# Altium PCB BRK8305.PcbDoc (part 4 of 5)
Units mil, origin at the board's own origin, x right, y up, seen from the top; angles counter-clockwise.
Board outline 5944.89 x 4139.76 mil, 4 copper layers (L1-Top, L2-GND, L3-GND, L4-BOT), stack 61.2 mil thick; 237 components, 286 nets, 1257 pads, 698 vias.
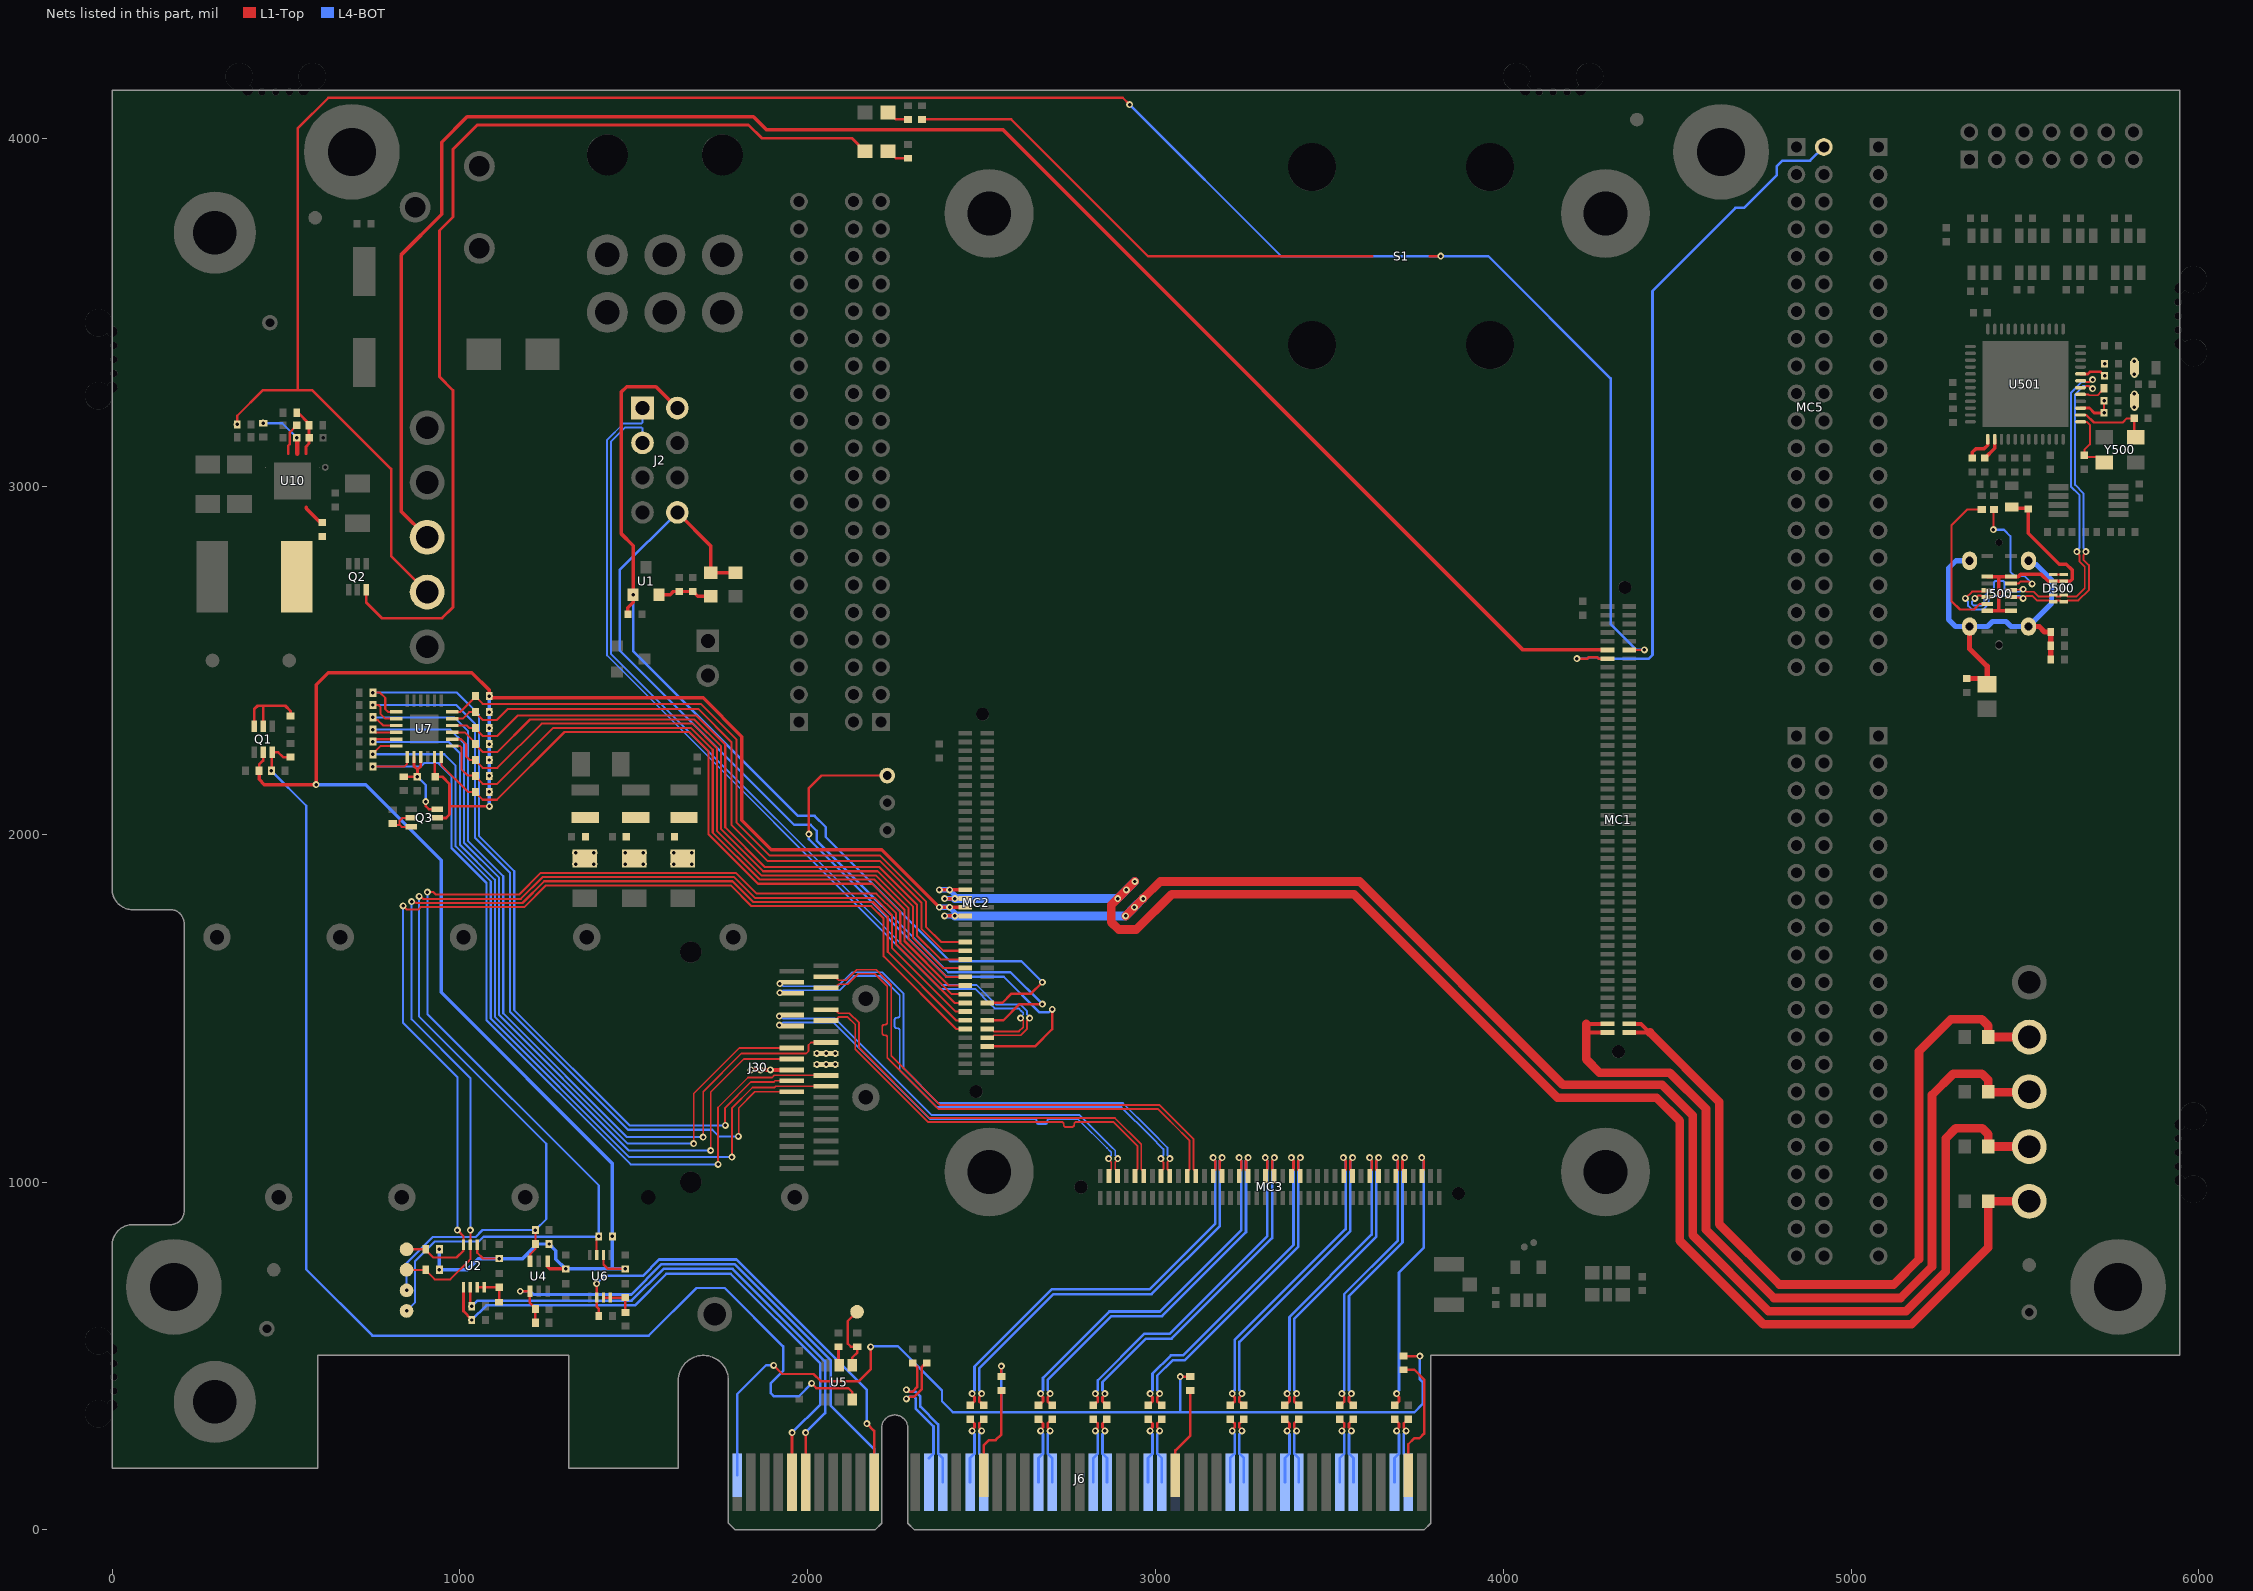
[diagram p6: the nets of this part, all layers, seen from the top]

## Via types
v1: diameter 20, hole 10, L1-Top to L4-BOT, tented both sides, 698 vias

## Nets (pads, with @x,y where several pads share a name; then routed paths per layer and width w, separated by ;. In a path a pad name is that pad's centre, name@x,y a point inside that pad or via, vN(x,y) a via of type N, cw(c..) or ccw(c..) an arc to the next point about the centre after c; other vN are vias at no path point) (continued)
MGT_TXN0_225: C20.2 MC3.47 | length 973.6
  L1-Top w7.5: v1(3011.8,391.89) 3011.8,388.51 3004.77,381.48 3004.77,369.54 3009.17,365.15 3011.22,365.15 C20.2@3017.71,358.66 ; MC3.47@3415.75,1017.72 3415.75,1030.51 3410,1036.26 3410,1061.23 3416.25,1067.48 v1(3416.25,1070.87)
  L4-BOT w7.5: v1(3011.8,391.89) 3011.8,395.27 3004.77,402.3 3004.77,443.76 3049.48,488.47 3084.32,488.47 3410,814.14 3410,1061.23 3416.25,1067.48 v1(3416.25,1070.87)
MGT_TXN0_226: J30.37 MC3.23 | length 1505.4
  L1-Top w5.25: J30.37@2052.5,1590.59 2081.05,1590.59 2085.31,1586.33 2085.31,1583.54 2088.39,1580.47 2110.73,1580.47 2140.96,1610.7 2196.61,1610.7 2239.87,1567.44 2239.87,1363.05 2381.42,1221.5 3011.81,1221.5 3108.87,1124.43 3108.87,1037.39 3115.75,1030.51 MC3.23@3115.75,1017.72
MGT_TXN1_224: C26.2 MC3.71 | length 849.1
  L1-Top w7.5: v1(3562.98,391.89) 3562.98,388.51 3555.95,381.48 3555.95,369.54 3560.35,365.15 3562.4,365.15 C26.2@3568.89,358.66 ; MC3.71@3715.75,1017.72 3715.75,1030.51 3710,1036.26 3710,1061.23 3716.25,1067.48 v1(3716.25,1070.87)
  L4-BOT w7.5: v1(3562.98,391.89) 3562.98,395.27 3555.95,402.3 3555.95,672.7 3710,826.74 3710,1061.23 3716.25,1067.48 v1(3716.25,1070.87)
MGT_TXN1_225: C18.2 MC3.41 | length 1030.4
  L1-Top w7.5: v1(2854.32,391.89) 2854.32,388.51 2847.29,381.48 2847.29,369.54 2851.69,365.15 2853.74,365.15 C18.2@2860.23,358.66 ; MC3.41@3340.75,1017.72 3340.75,1030.51 3335,1036.26 3335,1061.23 3341.25,1067.48 v1(3341.25,1070.87)
  L4-BOT w7.5: v1(2854.32,391.89) 2854.32,395.27 2847.29,402.3 2847.29,424.95 2972.63,550.29 3046.15,550.29 3335,839.14 3335,1061.23 3341.25,1067.48 v1(3341.25,1070.87)
MGT_TXN1_226: J30.2 MC3.17 | length 1559.6
  L1-Top w5.25: MC3.17@3040.75,1017.72 3040.75,1030.51 3033.87,1037.39 3033.87,1057.03 3041.25,1064.41 v1(3041.25,1067.48)
  L4-BOT w5.25: v1(1919.62,1570.72) 1922.7,1570.72 1930.07,1563.35 2086.63,1563.35 2127.05,1603.77 2213.5,1603.77 2226.52,1590.75 2275.5,1541.77 2275.5,1327.09 2375.33,1227.27 2906.39,1227.27 2984.24,1149.41 3033.87,1099.78 3033.87,1077.93 3041.25,1070.56 v1(3041.25,1067.48)
MGT_TXN2_224: C24.2 MC3.65 | length 883.3
  L1-Top w7.5: v1(3405.5,391.89) 3405.5,388.51 3398.47,381.48 3398.47,369.54 3402.87,365.15 3404.92,365.15 C24.2@3411.41,358.66 ; MC3.65@3640.75,1017.72 3640.75,1030.51 3635,1036.26 3635,1061.23 3641.25,1067.48 v1(3641.25,1070.87)
  L4-BOT w7.5: v1(3405.5,391.89) 3405.5,395.27 3398.47,402.3 3398.47,606.91 3635,843.44 3635,1061.23 3641.25,1067.48 v1(3641.25,1070.87)
MGT_TXN2_225: C16.2 MC3.35 | length 1106.7
  L1-Top w7.5: v1(2696.84,391.89) 2696.84,388.51 2689.81,381.48 2689.81,369.54 2694.21,365.15 2696.26,365.15 C16.2@2702.75,358.66 ; MC3.35@3265.75,1017.72 3265.75,1030.51 3260,1036.26 3260,1061.23 3266.25,1067.48 v1(3266.25,1070.87)
  L4-BOT w7.5: v1(2696.84,391.89) 2696.84,395.27 2689.81,402.3 2689.81,431.71 2872.92,614.81 3018.37,614.81 3260,856.44 3260,1061.23 3266.25,1067.48 v1(3266.25,1070.87)
MGT_TXN2_226: J30.34 MC3.11 | length 1204.1
  L1-Top w5.25: J30.34@2052.5,1496.1 2081.05,1496.1 2085.31,1491.84 2085.31,1489.06 2088.39,1485.98 2119.58,1485.98 2147.58,1457.98 2147.58,1386.86 2349.83,1184.61 2883.15,1184.61 2958.87,1108.88 2958.87,1037.39 2965.75,1030.51 MC3.11@2965.75,1017.72
MGT_TXN3_224: C22.2 MC3.59 | length 917.4
  L1-Top w7.5: v1(3248.02,391.89) 3248.02,388.51 3240.99,381.48 3240.99,369.54 3245.39,365.15 3247.44,365.15 C22.2@3253.93,358.66 ; MC3.59@3565.75,1017.72 3565.75,1030.51 3560,1036.26 3560,1061.23 3566.25,1067.48 v1(3566.25,1070.87)
  L4-BOT w7.5: v1(3248.02,391.89) 3248.02,395.27 3240.99,402.3 3240.99,540.58 3560,859.59 3560,1061.23 3566.25,1067.48 v1(3566.25,1070.87)
MGT_TXN3_225: C14.2 MC3.29 | length 1237
  L1-Top w7.5: v1(2499.99,391.89) 2499.99,388.51 2492.96,381.48 2492.96,369.54 2497.36,365.15 2499.41,365.15 C14.2@2505.9,358.66 ; MC3.29@3190.75,1017.72 3190.75,1030.51 3185,1036.26 3185,1061.23 3191.25,1067.48 v1(3191.25,1070.87)
  L4-BOT w7.5: v1(2499.99,391.89) 2499.99,395.27 2492.96,402.3 2492.96,464.23 2706.95,678.22 2988.64,678.22 3185,874.58 3185,1061.23 3191.25,1067.48 v1(3191.25,1070.87)
MGT_TXN3_226: J30.5 MC3.5 | length 1244.6
  L1-Top w5.25: v1(1918.25,1477.61) 1921,1480.35 J30.5@1953.68,1480.35 ; MC3.5@2890.75,1017.72 2890.75,1030.51 2883.87,1037.39 2883.87,1057.03 2891.25,1064.41 v1(2891.25,1067.48)
  L4-BOT w5.25: v1(1918.25,1477.61) 1921.33,1477.61 1928.7,1470.23 2079.14,1470.23 2196.03,1353.35 2356.61,1192.77 2781.65,1192.77 2871.99,1102.43 2872.55,1102.43 2883.87,1091.11 2883.87,1077.93 2891.25,1070.56 v1(2891.25,1067.48)
MGT_TXP0_224: C29.2 MC3.75 | length 814.9
  L1-Top w7.5: C29.2@3687,358.66 3693.49,365.15 3695.54,365.15 3699.94,369.54 3699.94,381.48 3692.91,388.51 v1(3692.91,391.89) ; v1(3765.25,1070.87) 3765.25,1067.48 3771.5,1061.23 3771.5,1036.26 3765.75,1030.51 MC3.75@3765.75,1017.72
  L4-BOT w7.5: v1(3692.91,391.89) 3692.91,395.27 3699.94,402.3 3699.94,740.13 3771.5,811.69 3771.5,1061.23 3765.25,1067.48 v1(3765.25,1070.87)
MGT_TXP0_225: C19.2 MC3.45 | length 973.6
  L1-Top w7.5: C19.2@2978.34,358.66 2984.82,365.15 2986.88,365.15 2991.27,369.54 2991.27,381.48 2984.24,388.51 v1(2984.24,391.89) ; v1(3390.25,1070.87) 3390.25,1067.48 3396.5,1061.23 3396.5,1036.26 3390.75,1030.51 MC3.45@3390.75,1017.72
  L4-BOT w7.5: v1(2984.24,391.89) 2984.24,395.27 2991.27,402.3 2991.27,449.35 3043.89,501.97 3078.73,501.97 3396.5,819.73 3396.5,1061.23 3390.25,1067.48 v1(3390.25,1070.87)
MGT_TXP0_226: J30.36 MC3.21 | length 1505.4
  L1-Top w5.25: J30.36@2052.5,1559.1 2081.05,1559.1 2085.31,1563.36 2085.31,1566.14 2088.39,1569.22 2115.39,1569.22 2145.62,1599.45 2191.95,1599.45 2228.62,1562.78 2228.62,1491.84 2228.62,1458.96 cw(c2222.57,1458.96) 2222.57,1452.91 2220.15,1452.91 ccw(c2220.15,1446.86) 2214.1,1446.86 2214.1,1428.71 ccw(c2220.15,1428.71) 2220.15,1422.66 2222.57,1422.66 cw(c2222.57,1416.61) 2228.62,1416.61 2228.62,1394.33 2228.62,1358.39 2376.76,1210.25 3007.15,1210.25 3040.75,1176.64 3048.7,1168.69 3097.62,1119.77 3097.62,1037.39 3090.75,1030.51 MC3.21@3090.75,1017.72
MGT_TXP1_224: C25.2 MC3.69 | length 849.1
  L1-Top w7.5: C25.2@3529.52,358.66 3536.01,365.15 3538.06,365.15 3542.45,369.54 3542.45,381.48 3535.43,388.51 v1(3535.43,391.89) ; v1(3690.25,1070.87) 3690.25,1067.48 3696.5,1061.23 3696.5,1036.26 3690.75,1030.51 MC3.69@3690.75,1017.72
  L4-BOT w7.5: v1(3535.43,391.89) 3535.43,395.27 3542.45,402.3 3542.45,678.29 3696.5,832.33 3696.5,1061.23 3690.25,1067.48 v1(3690.25,1070.87)
MGT_TXP1_225: C17.2 MC3.39 | length 1030.4
  L1-Top w7.5: C17.2@2820.86,358.66 2827.34,365.15 2829.4,365.15 2833.79,369.54 2833.79,381.48 2826.76,388.51 v1(2826.76,391.89) ; v1(3315.25,1070.87) 3315.25,1067.48 3321.5,1061.23 3321.5,1036.26 3315.75,1030.51 MC3.39@3315.75,1017.72
  L4-BOT w7.5: v1(2826.76,391.89) 2826.76,395.27 2833.79,402.3 2833.79,430.54 2967.04,563.79 3040.56,563.79 3321.5,844.73 3321.5,1061.23 3315.25,1067.48 v1(3315.25,1070.87)
MGT_TXP1_226: J30.3 MC3.15 | length 1559.8
  L1-Top w5.25: v1(3015.25,1067.48) 3015.25,1064.41 3022.62,1057.03 3022.62,1037.39 3015.75,1030.51 MC3.15@3015.75,1017.72
  L4-BOT w5.25: v1(1919.62,1544.72) 1922.7,1544.72 1930.07,1552.1 2091.29,1552.1 2131.71,1592.52 2208.84,1592.52 2226.52,1574.84 2264.25,1537.11 2264.25,1511.85 2264.25,1478.98 cw(c2258.2,1478.98) 2258.2,1472.93 2255.68,1472.93 ccw(c2255.68,1466.88) 2249.63,1466.88 2249.63,1448.73 ccw(c2255.68,1448.73) 2255.68,1442.68 2258.2,1442.68 cw(c2258.2,1436.63) 2264.25,1436.63 2264.25,1398.71 2264.25,1322.44 2370.67,1216.02 2901.73,1216.02 2984.24,1133.5 3022.62,1095.13 3022.62,1077.93 3015.25,1070.56 v1(3015.25,1067.48)
MGT_TXP2_224: C23.2 MC3.63 | length 883.3
  L1-Top w7.5: C23.2@3372.04,358.66 3378.53,365.15 3380.58,365.15 3384.97,369.54 3384.97,381.48 3377.94,388.51 v1(3377.94,391.89) ; v1(3615.25,1070.87) 3615.25,1067.48 3621.5,1061.23 3621.5,1036.26 3615.75,1030.51 MC3.63@3615.75,1017.72
  L4-BOT w7.5: v1(3377.94,391.89) 3377.94,395.27 3384.97,402.3 3384.97,612.5 3621.5,849.03 3621.5,1061.23 3615.25,1067.48 v1(3615.25,1070.87)
MGT_TXP2_225: C15.2 MC3.33 | length 1106.7
  L1-Top w7.5: C15.2@2663.38,358.66 2669.86,365.15 2671.92,365.15 2676.31,369.54 2676.31,381.48 2669.28,388.51 v1(2669.28,391.89) ; v1(3240.25,1070.87) 3240.25,1067.48 3246.5,1061.23 3246.5,1036.26 3240.75,1030.51 MC3.33@3240.75,1017.72
  L4-BOT w7.5: v1(2669.28,391.89) 2669.28,395.27 2676.31,402.3 2676.31,437.3 2867.33,628.31 3012.78,628.31 3246.5,862.03 3246.5,1061.23 3240.25,1067.48 v1(3240.25,1070.87)
MGT_TXP2_226: J30.33 MC3.9 | length 1204.1
  L1-Top w5.25: J30.33@2052.5,1464.61 2081.05,1464.61 2085.31,1468.87 2085.31,1471.65 2088.39,1474.73 2114.92,1474.73 2136.33,1453.32 2136.33,1382.2 2345.17,1173.36 2696.84,1173.36 2729.72,1173.36 cw(c2729.72,1167.31) 2735.77,1167.31 2735.77,1164.9 ccw(c2741.82,1164.9) 2741.82,1158.85 2759.97,1158.85 ccw(c2759.97,1164.9) 2766.02,1164.9 2766.02,1167.31 cw(c2772.07,1167.31) 2772.07,1173.36 2804.23,1173.36 2878.49,1173.36 2933.86,1117.99 2941.81,1110.03 2947.62,1104.22 2947.62,1037.39 2940.75,1030.51 MC3.9@2940.75,1017.72
MGT_TXP3_224: C21.2 MC3.57 | length 917.4
  L1-Top w7.5: C21.2@3214.56,358.66 3221.05,365.15 3223.1,365.15 3227.49,369.54 3227.49,381.48 3220.46,388.51 v1(3220.46,391.89) ; v1(3540.25,1070.87) 3540.25,1067.48 3546.5,1061.23 3546.5,1036.26 3540.75,1030.51 MC3.57@3540.75,1017.72
  L4-BOT w7.5: v1(3220.46,391.89) 3220.46,395.27 3227.49,402.3 3227.49,546.17 3546.5,865.18 3546.5,1061.23 3540.25,1067.48 v1(3540.25,1070.87)
MGT_TXP3_225: C13.2 MC3.27 | length 1237
  L1-Top w7.5: C13.2@2466.53,358.66 2473.01,365.15 2475.07,365.15 2479.46,369.54 2479.46,381.48 2472.43,388.51 v1(2472.43,391.89) ; v1(3165.25,1070.87) 3165.25,1067.48 3171.5,1061.23 3171.5,1036.26 3165.75,1030.51 MC3.27@3165.75,1017.72
  L4-BOT w7.5: v1(2472.43,391.89) 2472.43,395.27 2479.46,402.3 2479.46,469.82 2701.36,691.72 2983.05,691.72 3171.5,880.17 3171.5,1061.23 3165.25,1067.48 v1(3165.25,1070.87)
MGT_TXP3_226: J30.6 MC3.3 | length 1240.9
  L1-Top w5.25: v1(1918.25,1451.61) J30.6@1950.94,1451.61 ; v1(2865.25,1067.48) 2865.25,1064.41 2872.62,1057.03 2872.62,1037.39 2865.75,1030.51 MC3.3@2865.75,1017.72
  L4-BOT w5.25: v1(1918.25,1451.61) 1921.33,1451.61 1928.7,1458.98 2074.48,1458.98 2180.12,1353.35 2351.95,1181.52 2619.43,1181.52 2652.31,1181.52 cw(c2652.31,1175.47) 2658.36,1175.47 2658.36,1172.98 ccw(c2664.41,1172.98) 2664.41,1166.93 2682.56,1166.93 ccw(c2682.56,1172.98) 2688.61,1172.98 2688.61,1175.47 cw(c2694.66,1175.47) 2694.66,1181.52 2724.4,1181.52 2776.99,1181.52 2860.23,1098.28 2868.99,1089.52 2869.55,1089.52 2872.62,1086.45 2872.62,1077.93 2865.25,1070.56 v1(2865.25,1067.48)
NetC2_2: C2.2 C3.1 R5.1 U1.2 | length 158
  L1-Top w10: U1.2@1572.77,2689.06 1604.26,2689.06 1613.55,2698.35 C3.1@1630.62,2698.35 1670.44,2698.35 1683.82,2684.96 R5.1@1721.39,2684.96
NetC10_2: C10.2 R13.1 U2.7 U2.8 | length 106.1
  L1-Top w7: U2.7@1049.49,698.26 1049.89,697.86 C10.2@1112.49,697.86 R13.1@1112.49,654.95
NetC28_2: C28.2 R23.1 U6.7 U6.8 | length 105.8
  L1-Top w7.5: U6.7@1412.68,668.73 1413.47,667.94 C28.2@1475.67,667.94 R23.1@1475.67,625.42
NetC36_2: C36.2 Q3.6 R38.1 U7.20 U7.21 | length 271.6
  L1-Top w7: v1(901.57,2094.49) 901.57,2081.5 910.24,2072.83 Q3.6@934.65,2072.83
  L1-Top w8: R38.1@838.19,2165.35 R38.1@838.39,2165.55 877.36,2165.55 C36.2@877.46,2165.65 v1(877.56,2165.75) 877.56,2186.08 ; U7.20@867.72,2222.44 867.72,2195.92 877.56,2186.08 ; U7.21@887.4,2222.44 887.4,2195.92 877.56,2186.08
  L4-BOT w7: v1(877.56,2165.75) 901.57,2141.73 v1(901.57,2094.49)
NetC53_1: C53.1 U10.12 | length 67.2
  L1-Top w10: 557.66,2941.07 557.66,2937.09 597.98,2896.77 C53.1@604.15,2896.77
NetC53_2: C53.2 L14.1 U10.9 U10.10 U10.11
NetC54_1: C54.1 R77.1 R78.2 U10.1 | length 138.8
  L1-Top w8: R78.2@530.84,3212.61 534.15,3212.61 566.47,3180.3 566.47,3176.61 R77.1@566.07,3176.22 566.07,3140.61 566.07,3123.53 557.05,3114.51 U10.1@557.05,3094.41
NetC55_2: C55.2 U10.3 | length 92.7
  L1-Top w7: U10.3@505.87,3094.41 505.87,3117.33 510.86,3122.32 510.86,3156.24 C55.2@531.23,3176.61
NetC90_2: C90.2 C91.2 J30.29 L6.2
  other v1: 2026.04,1338.62 2052.5,1338.62 2078.97,1338.62 1332.71,1914.32 1384.71,1914.32 1332.71,1947.24 1384.71,1947.24
NetC92_2: C92.2 C93.2 J30.10 L7.2 | length 116.9
  L1-Top w12: v1(1836.83,1322.87) v1(1864.6,1322.87) v1(1892.16,1322.87) J30.10@1953.68,1322.87
  other v1: 1475.43,1914.32 1527.43,1914.32 1475.43,1947.24 1527.43,1947.24
NetC94_2: C94.2 C95.2 J30.30 L5.2
  other v1: 2026.04,1370.12 2052.5,1370.12 2078.97,1370.12 1614.21,1914.32 1666.21,1914.32 1614.21,1947.24 1666.21,1947.24
NetC501_2: C501.2 C502.2 FB500.2 U501.8 | length 76.8
  L1-Top w8: U501.8@5659.6,3324.02 5680.54,3324.02 5686.45,3329.93 5716.88,3329.93 5721.87,3324.94 5722.46,3324.94 5728.69,3318.7 v1(5728.69,3318.11)
  other v1: 5814.52,3322.44 5728.69,3353.55 5814.52,3361.03
NetC505_2: C505.2 C506.2 FB501.2 U501.3 | length 108.8
  L1-Top w7: C506.2@5726.72,3247.25 v1(5726.92,3247.05) 5726.92,3212.01 v1(5727.12,3211.82)
  L1-Top w8: U501.3@5659.6,3225.59 5685.04,3225.59 5698.82,3211.82 v1(5727.12,3211.82)
  other v1: 5814.52,3227.96 5814.52,3266.54
NetC522_2: C522.2 FB503.1 J500.M1 J500.M2 J500.M3 J500.M4 R504.1 R505.1 R506.1 | length 1121
  L1-Top w15: C522.2@5331.84,2448.43 5350.17,2448.43 ; J500.M3@5340.5,2597.64 5340.5,2533.86 5390.9,2483.47 FB503.1@5390.9,2432.29 5374.77,2448.41 5350.19,2448.41 ; J500.M2@5509.79,2597.64 5540.5,2597.64 5556.25,2581.89 R506.1@5573.97,2581.89 R505.1@5573.97,2542.52 R504.1@5573.97,2503.15
  L4-BOT w15: J500.M4@5342.47,2786.62 5301.7,2786.62 5280.27,2765.19 5280.27,2617.61 5300.24,2597.64 5391.65,2597.64 5406.22,2612.2 5445.07,2612.2 5459.63,2597.64 J500.M2@5509.79,2597.64 5576.16,2664.01 5576.16,2732.36 5532.24,2776.28 5520.13,2776.28 J500.M1@5509.79,2786.62
NetC523_2: C523.2 U501.1 Y500.1 | length 189.8
  L1-Top w6: U501.1@5659.6,3186.22 5677.42,3186.22 5686.17,3177.47 5686.17,3121.26 5670.42,3105.52 C523.2@5670.42,3090.16 5675.75,3084.83 5711.77,3084.83 Y500.1@5727.51,3069.1
NetC524_2: C524.2 U501.2 Y500.3 | length 223.9
  L1-Top w6: U501.2@5659.6,3205.91 5676.33,3205.91 5697.98,3184.26 5780.66,3184.26 5792.47,3196.07 C524.2@5813.73,3196.07 5813.73,3146.26 Y500.3@5818.06,3141.93
NetD1_1: D1.1 Q2.6 | length 2911.4
  L1-Top w8: Q2.6@730.74,2703.2 730.74,2666.13 775.15,2621.72 948.49,2621.72 979.92,2653.16 979.92,3276.74 940.87,3315.79 940.87,3736.6 979.92,3775.66 979.92,3969.79 1049.79,4039.65 1829.88,4039.65 1867.68,4001.85 2126.28,4001.85 D1.1@2164.33,3963.8
NetD1_2: D1.2 R3.1 | length 65.2
  L1-Top w7: D1.2@2231.26,3963.8 2233.23,3963.8 2252.91,3944.12 R3.1@2288.34,3944.12
NetD2_2: D2.2 R4.1 | length 65.2
  L1-Top w7: D2.2@2231.26,4075.46 2233.23,4075.46 2252.91,4055.78 R4.1@2288.34,4055.78
NetD500_1,10: D500.1 D500.10 | length 30.5
  L1-Top w5: D500.1@5580.37,2747.25 D500.10@5610.88,2747.25
NetJ6_B17: J6.B17 R27.1 | length 275.9
  L1-Top w7.5: J6.B17@2505.9,157.48 2505.9,242.76 2521.71,258.56 2540.05,258.56 2556.62,275.13 R27.1@2556.62,401.57
NetJ6_B31: J6.B31 R28.1 | length 262.8
  L1-Top w7.5: J6.B31@3057.08,157.48 3057.08,228.89 3099.84,271.65 R28.1@3099.84,401.57 R28.1@3099.84,402.6
NetJ6_B48: J6.B48 R29.1 | length 373.8
  L1-Top w7: R29.1@3712.6,460.63 3744.09,460.63 3771.96,432.76 3771.96,277.13 3758.13,263.3 3743.28,263.3 3726.37,246.4 J6.B48@3726.37,157.48
NetJ500_A5: J500.A5 R500.2 | length 361
  L1-Top w6: v1(5409.07,2875.99) 5409.07,2932.74 R500.2@5410.58,2934.26 ; J500.A5@5459.2,2721.66 5482.05,2721.66 5487.91,2727.52 5509.74,2727.52 5516.93,2720.33 v1(5520.25,2720.33)
  L4-BOT w6: v1(5409.07,2875.99) 5439.32,2875.99 5457.83,2857.48 5457.83,2755.12 5469.64,2743.31 5497.28,2743.31 v1(5520.25,2720.33)
NetJ500_B5: J500.B5 R501.1 | length 442.7
  L1-Top w6: R501.1@5375.15,2934.26 5333.81,2934.26 5288.53,2888.98 5288.53,2670.85 5312.77,2646.61 5353.25,2646.61 5369.24,2662.6 J500.B5@5391.09,2662.6
NetQ1_5: Q1.5 Q1.6 R30.1 | length 238.6
  L1-Top w8: Q1.6@408.56,2310.7 408.56,2360.1 418.39,2369.92 432.18,2369.92 ; Q1.5@434.15,2310.7 434.15,2367.96 432.18,2369.92 ; R30.1@512.89,2340.22 512.89,2354.63 497.6,2369.92 432.18,2369.92
NetQ3_2: Q3.2 Q3.3 R37.1 | length 104.1
  L1-Top w6: R37.1@806.69,2027.56 826.38,2027.56 ; Q3.3@859.84,2021.65 832.28,2021.65 826.38,2027.56 ; Q3.2@859.84,2047.24 834.25,2047.24 826.38,2039.37 826.38,2027.56
NetR1_1: R1.1 S1.2 | length 1457.3
  L1-Top w7: R1.1@2328.64,4055.78 2584.97,4055.78 2978.37,3662.38 S1.2@3623.03,3662.38
NetR18_1: R18.1 TP21.1 U5.4 | length 193.1
  L1-Top w7: U5.4@2127.94,473.62 2127.94,495.7 2142.43,510.18 R18.1@2142.43,526.77 2124.02,526.77 2114.92,535.88 2114.92,600.58 TP21.1@2141.72,627.39
NetR24_2: R24.2 U5.5 | length 54
  L1-Top w8: R24.2@2088.57,526.77 2088.57,475.59 U5.5@2090.54,473.62
NetR502_2: R502.2 U501.5 | length 78
  L1-Top w5.5: U501.5@5659.6,3264.96 5681.35,3264.96 5683.77,3262.54 5708.29,3262.54 5719.37,3273.62 5720.02,3273.62 5727.12,3280.71 R502.2@5727.12,3282.68
PCIE_PERST_B_3V3: J6.A11 R21.1 R22.2 U4.4 | length 1574
  L1-Top w7.5: v1(1173.23,686.44) U4.4@1201.07,686.44 1201.07,652.98 1216.82,637.23 R21.1@1216.82,635.26 R22.2@1216.82,595.89
  L4-BOT w7.5: v1(1173.23,686.44) 1203.32,686.44 1212.6,677.17 1492.72,677.17 1579.89,764.34 1789.51,764.34 2065.69,488.15 2065.69,358.36 2190.94,233.12 J6.A11@2190.94,137.79
PCIE_PERST_B_VIO: MC2.15 R12.2 R20.1 TP13.1 U4.3 | length 3522.7
  L1-Top w6: v1(882.44,1821.91) 886.23,1821.91 893.5,1814.65 1174.64,1814.65 1237.24,1877.25 1788.39,1877.25 1848.03,1817.61 2192.4,1817.61 2241.93,1768.08 2241.93,1673.97 2425.35,1490.55 MC2.15@2452.76,1490.55 ; U4.3@1201.07,773.06 1202.15,774.14 1202.15,792.79 1216.82,807.46 R20.1@1216.82,822.27 v1(1216.82,862.49)
  L4-BOT w6: v1(846.46,688.98) 846.46,767.72 920.93,842.2 1044.49,842.2 1064.78,862.49 v1(1216.82,862.49) 1248.03,893.7 1248.03,1110.59 882.44,1476.18 v1(882.44,1821.91)
PCIE_PRSNT1_B: J6.A1 R27.2 R28.2 R29.2 | length 2925.9
  L1-Top w7: v1(1901.57,473.58) 1926.61,448.54 2016.79,448.54 2037.46,427.87 2146.73,427.87 2180.61,461.74 v1(2180.61,526.74) ; R27.2@2556.62,440.94 v1(2556.62,470.94) ; v1(3070.87,440.94) R28.2@3099.84,440.94 ; R29.2@3712.6,500 v1(3759.84,500)
  L4-BOT w7: J6.A1@1797.24,157.48 1797.24,390.55 1880.27,473.58 v1(1901.57,473.58) ; v1(2180.61,526.74) 2182.06,528.19 2259.21,528.19 2385.83,401.57 2385.83,370.08 2417.32,338.58 2555.12,338.58 ; v1(2556.62,470.94) 2556.62,340.08 2555.12,338.58 ; v1(3070.87,440.94) 3070.87,338.58 ; v1(3759.84,500) 3759.84,433.07 3767.72,425.2 3767.72,362.2 3744.09,338.58 3070.87,338.58 ; 2555.12,338.58 3070.87,338.58
PCIE_REFCLKN_C: C8.1 J6.A14 | length 442.2
  L1-Top w7.5: v1(2283.67,403.25) 2287.05,403.25 2293.3,397 2300.91,397 2314.41,410.5 2314.41,468.5 ; C8.1@2302.25,480.07 2308.74,473.58 C8.1@2309.33,473.58 ; C8.1@2309.33,473.58 2310.01,473.58 2314.41,469.19 2314.41,468.5 ; C8.1@2309.33,473.58 2314.41,468.5
  L4-BOT w7.5: v1(2283.67,403.25) 2284.1,403.25 2290.35,397 2310.7,397 2323.51,384.19 2323.51,355.07 2374.85,303.73 2374.85,219.63 2387.79,206.69 J6.A14@2387.79,137.79
PCIE_REFCLKP_C: C7.1 J6.A13 | length 375
  L1-Top w7.5: v1(2283.67,377.25) 2287.05,377.25 2293.3,383.5 2306.5,383.5 2327.91,404.91 2327.91,468.41 ; C7.1@2341.62,480.07 2335.13,473.58 C7.1@2333.08,473.58 ; 2327.91,468.41 2327.91,469.19 2332.3,473.58 C7.1@2333.08,473.58 ; 2327.91,468.41 C7.1@2333.08,473.58
  L4-BOT w7.5: v1(2283.67,377.25) 2284.1,377.25 2290.35,383.5 2305.11,383.5 2310.01,378.6 2310.01,349.48 2361.35,298.14 2361.35,219.63 J6.A13@2348.42,206.69
PCIE_RX0N_C: C14.1 J6.A17 | length 197.6
  L1-Top w7.5: v1(2499.99,285.27) 2499.99,287.89 2492.96,294.92 2492.96,306.16 2498.82,312.02 2499.41,312.02 C14.1@2505.9,318.5
  L4-BOT w7.5: v1(2499.99,285.27) 2499.99,282.66 2492.96,275.63 2492.96,219.63 2505.9,206.69 J6.A17@2505.9,137.79
PCIE_RX0P_C: C13.1 J6.A16 | length 197.6
  L1-Top w7.5: C13.1@2466.53,318.5 2473.01,312.02 2473.6,312.02 2479.46,306.16 2479.46,294.92 2472.43,287.89 v1(2472.43,285.27)
  L4-BOT w7.5: J6.A16@2466.53,137.79 2466.53,206.69 2479.46,219.63 2479.46,275.63 2472.43,282.66 v1(2472.43,285.27)
PCIE_RX1N_C: C16.1 J6.A22 | length 197.6
  L1-Top w7.5: v1(2696.84,285.27) 2696.84,287.89 2689.81,294.92 2689.81,306.16 2695.67,312.02 2696.26,312.02 C16.1@2702.75,318.5
  L4-BOT w7.5: v1(2696.84,285.27) 2696.84,282.66 2689.81,275.63 2689.81,219.63 2702.75,206.69 J6.A22@2702.75,137.79
PCIE_RX1P_C: C15.1 J6.A21 | length 197.6
  L1-Top w7.5: C15.1@2663.38,318.5 2669.86,312.02 2670.45,312.02 2676.31,306.16 2676.31,294.92 2669.28,287.89 v1(2669.28,285.27)
  L4-BOT w7.5: J6.A21@2663.38,137.79 2663.38,206.69 2676.31,219.63 2676.31,275.63 2669.28,282.66 v1(2669.28,285.27)
PCIE_RX2N_C: C18.1 J6.A26 | length 197.6
  L1-Top w7.5: v1(2854.32,285.27) 2854.32,287.89 2847.29,294.92 2847.29,306.16 2853.15,312.02 2853.74,312.02 C18.1@2860.23,318.5
  L4-BOT w7.5: v1(2854.32,285.27) 2854.32,282.66 2847.29,275.63 2847.29,219.63 2860.23,206.69 J6.A26@2860.23,137.79
PCIE_RX2P_C: C17.1 J6.A25 | length 197.6
  L1-Top w7.5: C17.1@2820.86,318.5 2827.34,312.02 2827.94,312.02 2833.79,306.16 2833.79,294.92 2826.76,287.89 v1(2826.76,285.27)
  L4-BOT w7.5: J6.A25@2820.86,137.79 2820.86,206.69 2833.79,219.63 2833.79,275.63 2826.76,282.66 v1(2826.76,285.27)
PCIE_RX3N_C: C20.1 J6.A30 | length 197.6
  L1-Top w7.5: v1(3011.8,285.27) 3011.8,287.89 3004.77,294.92 3004.77,306.16 3010.63,312.02 3011.22,312.02 C20.1@3017.71,318.5
  L4-BOT w7.5: v1(3011.8,285.27) 3011.8,282.66 3004.77,275.63 3004.77,219.63 3017.71,206.69 J6.A30@3017.71,137.79
PCIE_RX3P_C: C19.1 J6.A29 | length 197.6
  L1-Top w7.5: C19.1@2978.34,318.5 2984.82,312.02 2985.42,312.02 2991.27,306.16 2991.27,294.92 2984.24,287.89 v1(2984.24,285.27)
  L4-BOT w7.5: J6.A29@2978.34,137.79 2978.34,206.69 2991.27,219.63 2991.27,275.63 2984.24,282.66 v1(2984.24,285.27)
PCIE_RX4N_C: C22.1 J6.A36 | length 197.6
  L1-Top w7.5: v1(3248.02,285.27) 3248.02,287.89 3240.99,294.92 3240.99,306.16 3246.85,312.02 3247.44,312.02 C22.1@3253.93,318.5
  L4-BOT w7.5: v1(3248.02,285.27) 3248.02,282.66 3240.99,275.63 3240.99,219.63 3253.93,206.69 J6.A36@3253.93,137.79
PCIE_RX4P_C: C21.1 J6.A35 | length 197.6
  L1-Top w7.5: C21.1@3214.56,318.5 3221.05,312.02 3221.64,312.02 3227.49,306.16 3227.49,294.92 3220.46,287.89 v1(3220.46,285.27)
  L4-BOT w7.5: J6.A35@3214.56,137.79 3214.56,206.69 3227.49,219.63 3227.49,275.63 3220.46,282.66 v1(3220.46,285.27)
PCIE_RX5N_C: C24.1 J6.A40 | length 197.6
  L1-Top w7.5: v1(3405.5,285.27) 3405.5,287.89 3398.47,294.92 3398.47,306.16 3404.33,312.02 3404.92,312.02 C24.1@3411.41,318.5
  L4-BOT w7.5: v1(3405.5,285.27) 3405.5,282.66 3398.47,275.63 3398.47,219.63 3411.41,206.69 J6.A40@3411.41,137.79
PCIE_RX5P_C: C23.1 J6.A39 | length 197.6
  L1-Top w7.5: C23.1@3372.04,318.5 3378.53,312.02 3379.12,312.02 3384.97,306.16 3384.97,294.92 3377.94,287.89 v1(3377.94,285.27)
  L4-BOT w7.5: J6.A39@3372.04,137.79 3372.04,206.69 3384.97,219.63 3384.97,275.63 3377.94,282.66 v1(3377.94,285.27)
PCIE_RX6N_C: C26.1 J6.A44 | length 197.6
  L1-Top w7.5: v1(3562.98,285.27) 3562.98,287.89 3555.95,294.92 3555.95,306.16 3561.81,312.02 3562.4,312.02 C26.1@3568.89,318.5
  L4-BOT w7.5: v1(3562.98,285.27) 3562.98,282.66 3555.95,275.63 3555.95,219.63 3568.89,206.69 J6.A44@3568.89,137.79
PCIE_RX6P_C: C25.1 J6.A43 | length 197.6
  L1-Top w7.5: C25.1@3529.52,318.5 3536.01,312.02 3536.6,312.02 3542.45,306.16 3542.45,294.92 3535.43,287.89 v1(3535.43,285.27)
  L4-BOT w7.5: J6.A43@3529.52,137.79 3529.52,206.69 3542.45,219.63 3542.45,275.63 3535.43,282.66 v1(3535.43,285.27)
PCIE_RX7N_C: C30.1 J6.A48 | length 197.6
  L1-Top w7.5: v1(3720.46,285.27) 3720.46,287.89 3713.44,294.92 3713.44,306.16 3719.29,312.02 3719.88,312.02 C30.1@3726.37,318.5
  L4-BOT w7.5: v1(3720.46,285.27) 3720.46,282.66 3713.44,275.63 3713.44,219.63 3726.37,206.69 J6.A48@3726.37,137.79
PCIE_RX7P_C: C29.1 J6.A47 | length 197.6
  L1-Top w7.5: C29.1@3687,318.5 3693.49,312.02 3694.08,312.02 3699.94,306.16 3699.94,294.92 3692.91,287.89 v1(3692.91,285.27)
  L4-BOT w7.5: J6.A47@3687,137.79 3687,206.69 3699.94,219.63 3699.94,275.63 3692.91,282.66 v1(3692.91,285.27)
PCIE_SMCLK_3V3: J6.B5 R17.1 U2.5 | length 1643.2
  L1-Top w7.5: U2.5@1010.12,698.26 1010.12,629.36 1033.75,605.74 v1(1033.75,603.77) ; J6.B5@1954.72,137.79 v1(1954.72,280.12)
  L4-BOT w7.5: v1(1033.75,603.77) 1075.65,645.67 1502.53,645.67 1593.61,736.75 1778.08,736.75 2036.02,478.8 2036.02,361.43 v1(1954.72,280.12)
PCIE_SMCLK_VIO: MC2.11 R14.1 TP12.1 U2.4 | length 3141.9
  L1-Top w6: TP12.1@834.65,807.09 TP12.1@846.46,807.09 R14.1@901.57,807.09 901.57,805.12 923.23,783.46 990.16,783.46 1010.12,803.43 U2.4@1010.12,820.3 1010.12,845.08 v1(992.72,862.49) ; v1(836.64,1794.7) 847.69,1783.65 880.15,1783.65 887.15,1790.65 1184.58,1790.65 1247.18,1853.25 1778.45,1853.25 1838.09,1793.61 2182.46,1793.61 2217.93,1758.14 2217.93,1649.61 2426.99,1440.55 MC2.11@2452.76,1440.55
  L4-BOT w6: v1(836.64,1794.7) 836.64,1457.85 992.72,1301.77 v1(992.72,862.49)
PCIE_SMDAT_3V3: J6.B6 R16.1 U2.6 | length 1597.9
  L1-Top w7.5: U2.6@1029.91,698.15 1029.91,646.97 v1(1033.75,643.14) ; J6.B6@1994.09,137.79 v1(1994.09,280.27)
  L4-BOT w7.5: v1(1033.75,643.14) 1049.78,659.17 1493.81,659.17 1585.48,750.84 1783.91,750.84 2050.11,484.64 2050.11,336.3 v1(1994.09,280.27)
PCIE_SMDAT_VIO: MC2.13 R15.1 TP9.1 U2.3 | length 3159.6
  L1-Top w6: TP9.1@846.46,744.09 850.39,748.03 R15.1@901.57,748.03 ; v1(860.92,1806.85) 863.6,1804.17 873.32,1804.17 874.84,1802.65 1179.61,1802.65 1242.21,1865.25 1783.42,1865.25 1843.06,1805.61 2187.43,1805.61 2229.93,1763.11 2229.93,1662.27 2427.59,1464.62 2451.83,1464.62 MC2.13@2452.76,1465.55 ; R15.1@905.51,744.09 905.51,742.13 927.17,720.47 972.44,720.47 1029.81,777.84 U2.3@1029.81,820.3 v1(1029.81,862.49)
  L4-BOT w6: v1(860.92,1806.85) 860.92,1468.43 1029.81,1299.54 v1(1029.81,862.49)
PCIE_WAKE_B_3V3: J6.B11 R26.1 U6.6 | length 1330.3
  L1-Top w7.5: v1(1393,708.66) U6.6@1393,668.73 1393,642.23 1398.9,636.33 R26.1@1398.9,615.58 ; v1(2170.06,306.16) 2190.94,285.29 J6.B11@2190.94,137.79
  L4-BOT w7.5: v1(1393,708.66) 1415.2,730.87 1525.62,730.87 1572.59,777.84 1795.1,777.84 2170.06,402.87 v1(2170.06,306.16)
PCIE_WAKE_B_VIO: MC2.17 R25.1 TP15.1 U6.3 | length 3742.8
  L1-Top w6: v1(906.12,1833.9) 923.79,1833.9 931.05,1826.65 1169.67,1826.65 1232.27,1889.25 1793.36,1889.25 1853,1829.61 2197.37,1829.61 2253.93,1773.05 2253.93,1683.48 2421.86,1515.55 MC2.17@2452.76,1515.55 ; U6.3@1393,790.78 1393,838.02 v1(1398.9,843.92)
  L4-BOT w6: v1(846.46,629.92) 870.4,653.86 870.4,771.97 927.78,829.35 1053.76,829.35 1067.44,843.03 1398.01,843.03 v1(1398.9,843.92) 1398.9,990.72 906.12,1483.5 v1(906.12,1833.9)
QSFP_INT_B_3V3: J30.28 R42.1 U7.19 | length 2460.5
  L1-Top w5: v1(1742.18,1051.45) 1741.82,1051.81 1741.82,1214.6 1828.26,1301.04 1897.54,1301.04 1903.63,1307.13 J30.28@2052.5,1307.13
  L1-Top w6: v1(749.61,2194.88) 840.16,2194.88 848.03,2202.76 U7.19@848.03,2222.44
  L4-BOT w6: v1(749.61,2194.88) 887.01,2194.88 897.24,2205.12 938.16,2205.12 975.62,2167.66 975.62,1960.85 1076.38,1860.1 1076.38,1465.8 1490.73,1051.45 v1(1742.18,1051.45)
QSFP_INT_B_VIO: MC2.19 R49.1 U7.24 | length 2151.9
  L1-Top w6: U7.24@946.46,2222.44 946.46,2198.82 1023.23,2122.05 R49.1@1044.88,2122.05 ; R49.1@1047.24,2117.72 1065.34,2099.62 1105.61,2099.62 1300.39,2294.41 1658.82,2294.41 1714.66,2238.57 1714.66,2000.24 1856.76,1858.14 2185.82,1858.14 2265.93,1778.02 2265.93,1688.45 2413.83,1540.55 MC2.19@2452.76,1540.55
QSFP_LP_MODE_3V3: J30.31 R43.1 U7.15 | length 2495.6
  L1-Top w5: v1(1699.16,1129.9) 1699.16,1260.15 1809.13,1370.12 1995.43,1370.12 2002.11,1376.8 2002.11,1394.33 2009.39,1401.61 J30.31@2052.5,1401.61
  L1-Top w6: v1(749.61,2336.61) 749.61,2335.26 756.45,2328.41 763.79,2328.41 779.21,2312.99 U7.15@816.54,2312.99
  L4-BOT w6: v1(749.61,2336.61) 984.03,2336.61 1023.62,2297.02 1023.62,1980.73 1124.38,1879.98 1124.38,1485.69 1479.96,1130.1 1698.96,1130.1 v1(1699.16,1129.9)
QSFP_LP_MODE_VIO: MC2.27 R41.1 U7.4 | length 1992.1
  L1-Top w6: U7.4@977.95,2312.99 1018.91,2312.99 1026.13,2305.77 R41.1@1044.88,2305.77 ; R41.1@1047.24,2303.15 1047.24,2301.44 1065.96,2282.73 1106.99,2282.73 1166.67,2342.41 1678.7,2342.41 1762.66,2258.45 1762.66,2020.12 1876.64,1906.14 2205.7,1906.14 2313.93,1797.9 2313.93,1708.94 2382.32,1640.55 MC2.27@2452.76,1640.55
QSFP_MODPRS_B_3V3: J30.27 R46.1 U7.18 | length 2393.9
  L1-Top w5: v1(1781.67,1072.08) 1781.91,1072.31 1781.91,1212.93 1841.09,1272.11 1904.63,1272.11 1908.15,1275.63 J30.27@2052.5,1275.63
  L1-Top w6: v1(749.61,2230.32) 749.61,2232.28 771.26,2253.94 U7.18@816.54,2253.94
  L4-BOT w6: v1(749.61,2230.32) 954.77,2230.32 987.62,2197.46 987.62,1965.82 1088.38,1865.07 1088.38,1470.77 1487.08,1072.08 v1(1781.67,1072.08)
QSFP_MODPRS_B_VIO: MC2.21 R48.1 U7.1 | length 2122.4
  L1-Top w6: U7.1@977.95,2253.94 1000.42,2253.94 1003.94,2250.42 1003.94,2187.45 1022.09,2169.29 1041.6,2169.29 1065.58,2145.31 1106.65,2145.31 1267.74,2306.41 1663.79,2306.41 1726.66,2243.54 1726.66,2005.21 1861.73,1870.14 2190.79,1870.14 2277.93,1782.99 2277.93,1693.42 2405.8,1565.55 MC2.21@2452.76,1565.55
QSFP_MODSEL_B_3V3: J30.8 R47.1 U7.16 | length 2364.4
  L1-Top w5: v1(1671.84,1111.04) 1671.84,1255.1 1802.61,1385.87 J30.8@1953.68,1385.87
  L1-Top w6: v1(749.61,2301.18) 749.61,2300.15 756.45,2293.31 U7.16@816.54,2293.31
  L4-BOT w6: v1(749.61,2301.18) 971.97,2301.18 1011.62,2261.53 1011.62,1975.76 1112.38,1875.01 1112.38,1480.71 1482.06,1111.04 v1(1671.84,1111.04)
QSFP_MODSEL_B_VIO: MC2.25 R44.1 U7.3 | length 2031.9
  L1-Top w6: U7.3@977.95,2293.31 1013.39,2293.31 1044.88,2261.81 R44.1@1044.88,2259.84 ; R44.1@1039.37,2259.84 1042.91,2259.84 1066.07,2236.69 1107.68,2236.69 1201.4,2330.41 1673.73,2330.41 1750.66,2253.48 1750.66,2015.15 1871.67,1894.14 2200.73,1894.14 2301.93,1792.93 2301.93,1703.36 2389.74,1615.55 MC2.25@2452.76,1615.55
QSFP_RESET_B_3V3: J30.9 R80.1 U7.17 | length 2354.3
  L1-Top w5: v1(1720.67,1091.12) 1720.67,1259.39 1815.65,1354.37 J30.9@1953.68,1354.37
  L1-Top w6: v1(749.61,2265.75) R80.1@749.61,2266.78 756.45,2273.62 U7.17@816.54,2273.62
  L4-BOT w6: v1(749.61,2265.75) 968.04,2265.75 999.62,2234.16 999.62,1970.79 1100.38,1870.04 1100.38,1475.74 1485.01,1091.12 v1(1720.67,1091.12)
QSFP_RESET_B_VIO: MC2.23 R45.1 U7.2 | length 2075.6
  L1-Top w6: U7.2@977.95,2273.62 1003.18,2273.62 1018.14,2258.66 1018.14,2223.78 1028.01,2213.91 R45.1@1044.88,2213.91 ; R45.1@1044.23,2212.6 1065.48,2191.35 1107.68,2191.35 1234.74,2318.41 1668.76,2318.41 1738.66,2248.51 1738.66,2010.18 1866.7,1882.14 2195.76,1882.14 2289.93,1787.96 2289.93,1698.39 2397.77,1590.55 MC2.23@2452.76,1590.55
QSFP_SCL_3V3: J30.11 R81.1 U7.13 | length 2349.6
  L1-Top w5: v1(1762.98,1163.57) 1762.32,1164.24 1762.32,1214.22 1836.11,1288.01 1902.84,1288.01 1906.21,1291.38 J30.11@1953.68,1291.38
  L1-Top w6: v1(749.61,2407.48) 769.97,2407.48 785.1,2392.35 785.1,2360.18 792.91,2352.36 U7.13@816.54,2352.36
  L4-BOT w6: v1(749.61,2407.48) 991.35,2407.48 1055.2,2343.63 1055.2,1995.04 1155.93,1894.31 1155.93,1494.89 1487.25,1163.57 v1(1762.98,1163.57)
QSFP_SCL_VIO: MC2.31 R39.1 U7.6 | length 1970.5
  L1-Top w6: U7.6@977.95,2352.36 1001.58,2352.36 1043.31,2394.09 R39.1@1043.31,2397.24 ; R39.1@1043.31,2397.64 R39.1@1043.31,2397.24 ; MC2.31@2452.76,1690.55 2383.65,1690.55 2339.61,1734.59 2339.61,1807.29 2208.02,1938.87 1890.2,1938.87 1795.39,2033.68 1795.39,2272.01 1692.26,2375.14 1065.41,2375.14 1044.88,2395.67 R39.1@1043.31,2397.24
QSFP_SDA_3V3: J30.12 R82.1 U7.14 | length 2339.7
  L1-Top w5: v1(1800.53,1131.66) 1801.24,1132.37 1801.24,1213.37 1847.76,1259.88 J30.12@1953.68,1259.88
  L1-Top w6: v1(749.61,2372.05) 765.85,2372.05 771.26,2366.64 771.26,2346.46 785.04,2332.68 U7.14@816.54,2332.68
  L4-BOT w6: v1(749.61,2372.05) 989.39,2372.05 1043.2,2318.24 1043.2,1990.07 1143.93,1889.34 1143.93,1489.92 1482.97,1150.88 1725.25,1150.88 1744.47,1131.66 v1(1800.53,1131.66)
QSFP_SDA_VIO: MC2.29 R40.1 U7.5 | length 1973.6
  L1-Top w6: U7.5@977.95,2332.68 1007.48,2332.68 1026.51,2351.71 R40.1@1044.88,2351.71 ; R40.1@1051.18,2350.39 1051.18,2343.44 1065.86,2328.76 1105.26,2328.76 1136.56,2360.06 1686.01,2360.06 1780.31,2265.76 1780.31,2027.43 1883.95,1923.79 2206.48,1923.79 2327.53,1802.75 2327.53,1727.8 2389.78,1665.55 MC2.29@2452.76,1665.55
RESERVED1: MC1.87 MC5.2 | length 2041.4
  L1-Top w7.5: v1(4211.24,2505.3) 4241.53,2505.3 4245.35,2509.12 4270.21,2509.12 4274.03,2505.3 MC1.87@4299.21,2505.3
  L4-BOT w7.5: v1(4211.24,2505.3) 4241.49,2505.3 4245.4,2509.21 4269.92,2509.21 4273.82,2505.3 4418.15,2505.3 4428.6,2515.75 4428.6,3562.45 4667.4,3801.26 4692.15,3801.26 4785.93,3895.04 4785.93,3919.79 4803.15,3937.01 4881.89,3937.01 MC5.2@4921.26,3976.38
USB_DN: D500.5 D500.6 J500.A7 J500.B7 U501.6 | length 1232
  L1-Top w5.6: v1(5328.53,2678.81) 5347.65,2697.93 5373.49,2697.93 5374.42,2698.87 5387.99,2698.87 J500.B7@5391.09,2701.97 ; J500.A7@5459.2,2682.29 5460.94,2680.55 5493.7,2680.55 5495.44,2678.81 5496.37,2678.81 5503.57,2686.01 5520.17,2686.01 5533.63,2672.55 5568.94,2672.55 5572.98,2668.51 D500.5@5580.37,2668.51 5587.75,2668.51 5589.87,2670.63 5589.87,2672.25 5590.17,2672.55 5601.07,2672.55 5601.37,2672.25 5601.37,2670.63 5603.5,2668.51 D500.6@5610.88,2668.51 5618.26,2668.51 5622.3,2672.55 5653.24,2672.55 5683.17,2702.48 5683.17,2774.23 5667.66,2789.74 5667.66,2802.71 5674.86,2809.91 v1(5674.86,2813.19) ; U501.6@5659.6,3284.65 5671.57,3284.65 5675.62,3288.69 5683.65,3288.69 5690.44,3281.9 v1@5694.22,3281.9
  L4-BOT w5.6: v1(5328.53,2678.81) 5328.53,2677.03 5336.23,2669.33 5336.23,2657.1 5346.3,2647.02 5380.41,2647.02 5394.64,2661.26 5394.64,2680.7 5399.95,2686.01 5415.2,2686.01 5484.61,2686.01 5491.81,2678.81 v1(5494.09,2678.81) ; v1(5674.86,2813.19) 5674.86,2816.47 5667.66,2823.67 5667.66,2980.68 5643.57,3004.77 5643.57,3265.3 5666.87,3288.6 5683.74,3288.6 5690.44,3281.9 v1@5694.22,3281.9
  other v1: 5694.22,3281.4
USB_DP: D500.4 D500.7 J500.A6 J500.B6 U501.7 | length 1232.8
  L1-Top w5.6: v1(5355.53,2678.81) 5357.49,2678.81 5365.01,2686.33 5373.49,2686.33 5374.42,2685.39 5387.99,2685.39 J500.B6@5391.09,2682.29 ; J500.A6@5459.2,2701.97 5460.62,2703.39 5494.02,2703.39 5495.44,2704.81 5496.37,2704.81 5503.57,2697.61 5524.97,2697.61 5538.43,2684.15 5568.94,2684.15 5572.98,2688.19 D500.4@5580.37,2688.19 5587.75,2688.19 5589.87,2686.07 5589.87,2684.46 5590.17,2684.15 5601.07,2684.15 5601.37,2684.46 5601.37,2686.07 5603.5,2688.19 D500.7@5610.88,2688.19 5618.26,2688.19 5622.3,2684.15 5648.43,2684.15 5671.57,2707.29 5671.57,2769.43 5656.06,2784.94 5656.06,2802.71 5648.86,2809.91 v1(5648.86,2813.19) ; U501.7@5659.6,3304.33 5671.57,3304.33 5675.62,3300.29 5683.74,3300.29 5690.35,3306.9 v1@5694.22,3306.9
  L4-BOT w5.6: v1(5355.53,2678.81) 5355.53,2677.03 5347.83,2669.33 5347.83,2661.9 5351.11,2658.62 5375.6,2658.62 5383.04,2666.06 5383.04,2685.5 5384.8,2687.27 5395.15,2697.61 5404.23,2697.61 ccw(c5404.23,2703.73) 5410.35,2703.73 5410.35,2722.83 cw(c5416.47,2722.83) 5416.47,2728.95 5434.83,2728.95 cw(c5434.83,2722.83) 5440.95,2722.83 5440.95,2703.73 ccw(c5447.07,2703.73) 5447.07,2697.61 5480.47,2697.61 5484.61,2697.61 5491.81,2704.81 v1(5494.09,2704.81) ; v1(5648.86,2813.19) 5648.86,2816.47 5656.06,2823.67 5656.06,2975.87 5631.97,2999.97 5631.97,3270.1 5662.07,3300.2 5683.74,3300.2 5690.44,3306.9 v1@5694.22,3306.9
  other v1: 5694.22,3307.4
VBATT: MC2.8 TP17.1 | length 1561.6
  L1-Top w7: v1(2003.25,2000.51) 2003.25,2133.38 2039.16,2169.29 TP17.1@2228.35,2169.29 ; MC2.8@2515.75,1390.55 2653.42,1390.55 2702.87,1440 v1(2702.87,1497.08)
  L4-BOT w7: v1(2003.25,2000.51) 2003.25,1985.85 2398.33,1590.77 2563.51,1590.77 2666.05,1488.23 2692.64,1488.23 2701.49,1497.08 v1(2702.87,1497.08)
VBUS_C: C510.2 D500.2 D500.9 FB502.2 J500.A4 J500.A9 J500.B4 J500.B9 | length 740.5
  L1-Top w10: J500.B4@5391.09,2642.92 5424.76,2642.92 ; J500.B9@5391.09,2741.34 5425.15,2741.34 ; J500.A9@5459.2,2642.92 5424.76,2642.92 ; FB502.2@5461.76,2940.95 5464.32,2938.39 5506.45,2938.39 C510.2@5509.01,2935.83 5509.01,2865.85 5597.68,2777.18 5618.68,2777.18 5635.58,2760.28 5635.58,2733.82 5629.33,2727.56 D500.9@5610.88,2727.56 D500.2@5580.37,2727.56 5566.16,2727.56 ; 5566.16,2727.74 5546.58,2747.32 5486.92,2747.32 5480.95,2741.34 5425.15,2741.34 ; 5424.76,2642.92 5424.76,2740.95 5425.15,2741.34
VCCA: C518.2 U501.37 | length 85.9
  L1-Top w10: C518.2@5348.57,3082.29 5348.57,3098.63 5359.4,3109.45 5383.02,3109.45 5392.87,3119.3 U501.37@5392.87,3136.03
VCCADC: C1.1 J2.2 MC2.18 U1.1 | length 2786.4
  L1-Top w7: MC2.18@2515.75,1515.55 2559.12,1515.55 2585.89,1542.33 2642.24,1542.33 v1(2674.76,1574.84)
  L1-Top w10: C1.1@1482.81,2632.55 1482.81,2651.92 1497.96,2667.08 v1(1497.96,2689.06) 1497.96,2830.35 1463.04,2865.27 1463.04,3270.88 1479.4,3287.24 1563.47,3287.24 J2.2@1624.88,3225.82
  L4-BOT w7: v1(1497.96,2689.06) 1497.96,2527.25 1972.03,2053.18 2019.42,2053.18 2051.51,2021.09 2051.51,1992.74 2408.9,1635.35 2614.25,1635.35 v1(2674.76,1574.84)
VCCO_64: MC1.2 MC1.4 R19.2 TP8.1 | length 2430.1
  L1-Top w12: MC1.2@4362.2,1430.3 4420.46,1430.3 4395.46,1455.3 MC1.4@4362.2,1455.3
  L1-Top w25: 4421.26,1430.3 4620.97,1230.6 4620.97,878.83 4794.11,705.69 5121.95,705.69 5195.21,778.94 5195.21,1376.8 5286.91,1468.49 5375.15,1468.49 5393.7,1449.94 R19.2@5393.7,1417.32 TP8.1@5511.81,1417.32
VCCO_84: MC1.1 MC1.3 R34.2 TP18.1 | length 2584.7
  L1-Top w12: 4237.92,1430.3 MC1.1@4299.21,1430.3 ; 4237.92,1455.3 MC1.3@4299.21,1455.3
  L1-Top w25: 4237.92,1455.3 4237.92,1430.3 4237.92,1353.63 4276.5,1315.05 4478.22,1315.05 4582.38,1210.89 4582.38,862.85 4778.13,667.1 5141.95,667.1 5232.49,757.63 5232.49,1250.7 5293.47,1311.68 5375.81,1311.68 5393.7,1293.79 R34.2@5393.7,1259.84 5393.7,1258.78 TP18.1@5511.81,1258.78
VCCO_85: C9.2 C11.2 C27.2 C35.2 MC2.37 MC2.39 Q1.2 Q3.5 R14.2 R15.2 R20.2 R25.2 R33.2 R35.2 R39.2 R40.2 R41.2 R44.2 R45.2 R48.2 R49.2 TP23.1 U2.2 U4.1 U6.2 U7.23 | length 10836.5
  L1-Top w7: R33.2@422.34,2182.74 422.34,2200.53 434.15,2212.34 Q1.2@434.15,2235.89 ; U2.2@1049.49,820.3 1049.49,797.24 1066.2,780.54 v1(1112.49,780.54) ; U6.2@1412.68,790.78 1412.68,763.02 1425.08,750.62 v1(1475.67,750.62)
  L1-Top w8: U7.23@926.77,2222.44 927.5,2221.72 927.5,2166.99 C35.2@928.74,2165.75 949.32,2165.75 970.23,2144.83 970.23,2080.71 ; Q3.5@934.65,2047.24 960.24,2047.24 970.23,2057.24 970.23,2080.71 ; v1(1084.25,2080.62) 1084.17,2080.71 970.23,2080.71
  L1-Top w10: R33.2@422.34,2182.74 422.34,2158.13 437.46,2143.01 v1(586.58,2143.01) 586.58,2430.15 621.55,2465.12 1034.32,2465.12 1084.25,2415.19 v1(1084.25,2397.64) 1084.25,2397.32 R39.2@1089.09,2392.48 ; R39.2@1084.25,2392.48 1699.27,2392.48 1810.64,2281.11 1810.64,2040.92 1895.23,1956.32 2212.3,1956.32 v1(2378.07,1790.55) v1(2407.6,1790.55) MC2.39@2452.76,1790.55 ; U4.1@1254.14,774.95 U4.1@1252.25,773.06 1252.25,756.48 1258.11,750.62 v1(1303.43,750.62) ; R20.2@1254.14,820.22 v1(1256.19,822.27) ; v1(2393.7,1765.55) v1(2423.23,1765.55) MC2.37@2452.76,1765.55
  L1-Top w25: v1(2914.04,1765.55) v1(2964.04,1815.55) 3013.04,1864.55 3586.63,1864.55 4170.79,1280.39 4455.89,1280.39 4544.4,1191.88 4544.4,847.12 4762.4,629.12 5157.68,629.12 5271.55,742.99 5271.55,1125.63 5300.78,1154.87 5376.48,1154.87 5393.7,1137.65 R35.2@5393.7,1102.36 TP23.1@5511.81,1102.36
  L4-BOT w10: v1(586.58,2143.01) 729.16,2143.01 946.46,1925.71 946.46,1545.71 1438.27,1053.89 v1(1438.27,843.92) 1438.27,755.82 1433.07,750.62 ; v1(940.95,807.09) v1(940.94,748.03) 1021.51,748.03 1054.01,780.54 v1(1112.49,780.54) 1180.29,780.54 1222.02,822.27 v1(1256.19,822.27) 1275.7,802.76 1275.7,778.35 v1(1303.43,750.62) 1433.07,750.62 ; v1@1082.68,2082.2 v1(1084.25,2080.62) v1(1084.25,2122.05) v1(1084.25,2167.98) v1(1084.25,2213.91) v1(1084.25,2259.84) v1(1084.25,2305.77) v1(1084.25,2351.71) v1(1084.25,2397.64) ; v1(1475.67,750.62) 1433.07,750.62
  L4-BOT w15: v1(2378.07,1790.55) v1(2407.6,1790.55) 2421.31,1776.83 2421.31,1767.46 v1(2423.23,1765.55) v1(2393.7,1765.55)
  L4-BOT w25: v1(2423.23,1765.55) v1(2914.04,1765.55) v1(2939.04,1790.55) v1(2964.04,1815.55)
VCCO_86: MC2.41 MC2.43 R36.2 TP25.1 | length 4534.5
  L1-Top w10: v1(2378.07,1840.55) v1(2407.6,1840.55) MC2.43@2452.76,1840.55 ; v1(2393.7,1815.55) v1(2423.23,1815.55) MC2.41@2452.76,1815.55
  L1-Top w25: v1(2940.25,1864.55) v1(2915.95,1840.26) v1(2891.25,1815.55) 2872.62,1796.93 2872.62,1747.44 2893.71,1726.35 2944.67,1726.35 3046.09,1827.77 3570.56,1827.77 4155.31,1243.02 4440.41,1243.02 4507.03,1176.4 4507.03,831.64 4746.92,591.75 5173.16,591.75 5393.7,812.29 R36.2@5393.7,944.88 TP25.1@5511.81,944.88
  L4-BOT w15: v1(2378.07,1840.55) v1(2407.6,1840.55) 2421.31,1826.83 2421.31,1817.46 v1(2423.23,1815.55) v1(2393.7,1815.55)
  L4-BOT w25: v1(2423.23,1815.55) v1(2891.25,1815.55) v1(2915.95,1840.26) v1(2940.25,1864.55)
VCORE: C517.2 U501.38 | length 65.9
  L1-Top w10: C517.2@5384.01,3082.29 5384.6,3082.29 5412.55,3110.24 U501.38@5412.55,3136.03
VIO_PG: Q1.3 R31.1 R32.2 U5.3 | length 3597.6
  L1-Top w7: v1(457.78,2182.74) 458.76,2183.73 458.76,2234.91 Q1.3@459.74,2235.89 477.49,2235.89 491.27,2222.11 R31.1@512.89,2222.11 ; v1(2011.03,421.26) 2024.7,407.59 2116.77,407.59 2127.94,396.41 U5.3@2127.94,375.2
  L4-BOT w7: v1(457.78,2182.74) 558.15,2082.36 558.15,748.93 748.03,559.06 1542.77,559.06 1679.51,695.8 1761.12,695.8 1929.13,527.79 1929.13,457.67 1894.1,422.64 1894.1,393.22 1903.13,384.19 1973.96,384.19 v1(2011.03,421.26)
VREF_64: MC1.89 TP22.1 | length 5232.2
  L1-Top w10: TP22.1@905.51,2854.33 830.55,2929.29 830.55,3665.89 947.7,3783.04 947.7,3990.49 1020.23,4063.02 1843.85,4063.02 1880.29,4026.57 2560.04,4026.57 4056.31,2530.3 MC1.89@4299.21,2530.3
VREFP: J2.8 MC2.14 R5.2 R6.2 | length 2581.8
  L1-Top w7: MC2.14@2515.75,1465.55 2562.28,1465.55 2608.58,1511.85 v1(2674.76,1511.85)
  L1-Top w10: J2.8@1624.88,2925.82 1721.39,2829.31 R5.2@1721.39,2751.89 R6.2@1792.04,2751.89
  L4-BOT w7: J2.8@1624.88,2925.82 1458.83,2759.77 1458.83,2529.61 1961.26,2027.18 2008.65,2027.18 2025.51,2010.32 2025.51,1981.97 2403.71,1603.77 2582.84,1603.77 v1(2674.76,1511.85)
VREG5: C56.2 R79.2 U10.2 | length 161.2
  L1-Top w13: C56.2@530.84,3140.61 531.46,3139.99 U10.2@531.46,3094.41 ; C56.2@531.23,3140.61 C56.2@531.46,3140.38
  L4-BOT w7: v1(434.15,3182.3) 489.15,3182.3 v1(531.15,3140.3)
XADC_VN_C: J2.3 MC2.10 | length 2564.9
  L1-Top w5.25: MC2.10@2515.75,1415.55 2528.54,1415.55 2535.42,1422.43 2611.84,1422.43 2630.68,1441.27 2630.68,1464.61 2637.73,1471.65 v1(2638.06,1471.65)
  L4-BOT w5.25: J2.3@1524.88,3125.82 1524.88,3167.12 1521.81,3170.2 1474.88,3170.2 1434.1,3129.41 1434.1,2518.95 2386.08,1566.97 2485.66,1566.97 2540.78,1511.85 2541.62,1511.01 2611.02,1511.01 2630.68,1491.34 2630.68,1482.1 2638.06,1474.73 v1(2638.06,1471.65)
XADC_VP_C: J2.1 MC2.12 | length 2564.9
  L1-Top w5.25: MC2.12@2515.75,1440.55 2528.54,1440.55 2535.42,1433.68 2607.18,1433.68 2619.43,1445.93 2619.43,1464.61 2612.39,1471.65 v1(2612.06,1471.65)
  L4-BOT w5.25: J2.1@1524.88,3225.82 1524.88,3184.52 1521.81,3181.45 1470.22,3181.45 1422.85,3134.07 1422.85,2514.29 2381.42,1555.72 2481,1555.72 2524.87,1511.85 2536.96,1499.76 2606.36,1499.76 2614.31,1491.81 2619.43,1486.68 2619.43,1482.1 2612.06,1474.73 v1(2612.06,1471.65)
XEM8305_PG: MC1.90 R76.2 S1.1 TP24.1 | length 6795.7
  L1-Top w5.25: MC1.90@4362.2,2530.3 v1(4405.45,2530.3)
  L1-Top w7: v1(359.48,3178.78) 359.48,3203.79 432.47,3276.77 534.15,3276.77 ; TP24.1@905.51,2696.85 801.81,2800.56 801.81,3050.97 576.01,3276.77 534.15,3276.77 ; v1(2925.2,4098.43) 2905.51,4118.11 621.5,4118.11 534.15,4030.76 534.15,3276.77 ; S1.1@3788.39,3662.4 v1(3819.88,3662.4)
  L4-BOT w7: v1(2925.2,4098.43) 3361.22,3662.4 v1(3819.88,3662.4) 3956.81,3662.4 4308.09,3311.12 4308.09,2605.09 4382.88,2530.3 v1(4405.45,2530.3)
pads on no net: D3.2 FID1.FID? FID2.FID? FID3.FID? FID4.FID? J2.4 J2.5 J2.6 J4.3 J5.0 J6.A5 J6.A6 J6.A7 J6.A8 J6.A19 J6.A32 J6.A33 J6.B9 J6.B12 J6.B30 J30.MH J500.A8 J500.B8 J500.M5 J500.M6 J501.12 J501.14 MB1.0 MB2.0 MB3.0 MB4.0 MB5.0 MB6.0 MC1. MC2. MC3. MC4.37 MC4.38 MC4.39 MC4.40 MC6.2 MC6.4 MC6.6 MH1.1 MH2.1 MH3.1 MH4.1 Q2.3 Q2.4 Q2.5 QSFP.0 S1.0 U3.2 U6.4 U6.5 U7.0 U7.7 U7.8 U7.9 U7.10 U7.11 U7.12 U501.17 U501.18 U501.19 U501.20 U501.21 U501.25 U501.26 U501.27 U501.28 U501.29 U501.30 U501.31 U501.32 U501.33 U505.6 U505.7
copper on no net:
  other v1: 4177.17,2155.3

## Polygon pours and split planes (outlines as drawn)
+VDCIN on L1-Top "+VDCIN_L01_P113" (solid, pour order 113): 1285.21,3572.61 1811.11,3572.61 1862.2,3623.71 1862.2,3772.87 1810.28,3824.8 1070.06,3824.8 968.5,3723.25 968.5,3371.87 1005.63,3334.74 1125.44,3334.74 1145.67,3354.97 1145.67,3433.07
+3.3V on L1-Top "+3.3V_L01_P110" (solid, pour order 110): 1287.43,1984.78 1287.43,2050.56 1320.54,2083.68 1687.02,2083.68 1699.26,2095.91 1699.26,2203.83 1624.75,2278.35 1315.06,2278.35 1030.47,1993.76 512.14,1993.76 340.15,2165.74 340.15,2352.72 400.15,2412.72 400.15,3006.61 237.01,3006.61 161.42,2931.02 161.42,2070.86 379.03,1853.25 1155.89,1853.25 1216.96,1914.32
NetC90_2 on L1-Top "NETC90_2_L01_P093" (solid, pour order 93): 1321.31,2064.27 1400.05,2064.27 1413.83,2050.49 1413.83,1924.5 1394.14,1904.82 1323.28,1904.82 1323.28,1960.92 1337.06,1974.7 1337.06,2009.15 1321.31,2024.9
NetC94_2 on L1-Top "NETC94_2_L01_P095" (solid, pour order 95): 1604.77,2064.27 1681.54,2064.27 1695.32,2050.49 1695.32,1924.5 1675.64,1904.82 1604.77,1904.82 1604.77,1960.92 1604.77,2022.93
NetC92_2 on L1-Top "NETC92_2_L01_P094" (solid, pour order 94): 1465.99,2064.27 1542.77,2064.27 1556.54,2050.49 1556.54,1924.5 1536.86,1904.82 1465.99,1904.82 1465.99,1960.92 1465.99,2022.93
+12V_PCIE_C on L1-Top "+12V_PCIE_C_L01_P089" (solid, pour order 89): 1791.45,351.2 1791.45,242.76 1891.94,242.76 1891.94,322.29 1863.03,351.2
NetC94_2 on L4-BOT "NONET_L-01_P-001" (solid, pour order 98): 2091.29,1346.91 2091.29,1400.56 2074.48,1417.36 1871.09,1417.36 1871.09,1794.55 1700.59,1965.05 1604.26,1965.05 1604.26,1510.8 1768.15,1346.91
+VDCIN on L4-BOT "NONET_L-01_P-001" (solid, pour order 92): 938.01,4139.76 2840.55,4139.76 2953.74,4026.57 2953.74,3686.69 3894.35,2742.13 4238.19,2742.13 4291.34,2688.98 4291.34,2554.69 4270.11,2533.46 3831.97,2533.46 2778.48,3586.95 2778.48,3863.25 2645.67,3996.06 2396.44,3996.06 2341.32,3940.94 2074.8,3940.94 2002.36,3868.5 1917.32,3868.5 1917.32,3752.74 1332.19,3752.74 1271.65,3692.21 1271.65,3376.56 974.71,3079.61 862.27,3079.61 748.1,2965.44 631.3,2965.44 631.3,3511.84 631.3,3705.08 656.53,3730.31 706.79,3730.31 874.39,3897.91 874.39,4076.14
FT232_VCCD on L4-BOT "FT232_VCCD_L04_P109" (solid, pour order 109): 5216.88,3556.3 5303.5,3642.92 5897.98,3642.92 5929.48,3611.42 5929.48,2953.51 5730.14,2754.18 5561.13,2754.18 5434.2,2881.11 5344.83,2881.11 5216.88,3009.06
NetC90_2 on L4-BOT "NONET_L-01_P-001" (solid, pour order 97): 2003.25,1334.67 2021.72,1353.35 2091.29,1353.35 2091.29,1309.13 2022.99,1241.63 1896.43,1241.63 1840.19,1185.39 1538.72,1185.39 1187.15,1536.97 1187.15,1856.44 1295.76,1965.05 1403.99,1965.05 1403.99,1497.59 1641.24,1260.33 1824.94,1260.33 1855.14,1290.53 1893.77,1290.06 1938.39,1334.67
NetC505_2 on L4-BOT "NETC505_2_L04_P106" (solid, pour order 106): 5709.79,3196.07 5709.79,3263 5731.84,3285.04 5825.54,3285.04 5835.78,3274.81 5835.78,3192.13 5812.16,3168.51 5733.42,3168.51
FT232_VREGIN on L4-BOT "FT232_VREGIN_L04_P108" (solid, pour order 108): 5435.23,2987.41 5425.06,2997.58 5425.06,3060.94 5473.57,3109.45 5516.88,3109.45 5543.99,3082.35 5543.99,3011.03 5520.36,2987.41
NetC501_2 on L4-BOT "NETC501_2_L04_P107" (solid, pour order 107): 5714.22,3313.69 5714.22,3374.24 5748.69,3408.71 5748.73,3408.67 5808.22,3408.67 5835.78,3381.11 5835.78,3310.24 5827.9,3302.37 5725.54,3302.37
+1.8V on L4-BOT "+1.8V_L04_P100" (solid, pour order 100): 2432.79,2295.28 2432.79,2233.66 2431.88,2233.66 2425.96,2227.74 2333.89,2227.74 2321.28,2240.35 2321.28,2281.28 2341.96,2301.95 2426.11,2301.95
NetC92_2 on L4-BOT "NONET_L-01_P-001" (solid, pour order 99): 1907.03,1338.62 1756.57,1338.62 1591.04,1504.15 1591.04,1965.05 1418.59,1965.05 1418.59,1507.49 1654.1,1271.97 1817.82,1271.97 1845.02,1299.17 1894.52,1299.17 1907.03,1311.68
DGND on L2-GND "DGND_L02_P090" (solid, pour order 90): 590.54,177.16 590.54,501.97 1312.98,501.97 1312.98,177.16 1627.94,177.16 1627.94,430.12 cw(c1699.8,430.12) 1771.65,430.12 1771.65,225.39 2212.59,225.39 2212.59,293.31 cw(c2249.99,293.31) 2287.39,293.31 2287.39,225.39 3791.33,225.39 3791.33,501.97 5944.88,501.97 5944.88,4139.76 -0.01,4139.76 -0.01,177.16
DGND on L3-GND "DGND_L03_P091" (solid, pour order 91): 590.54,177.16 590.54,501.97 1312.98,501.97 1312.98,177.16 1627.94,177.16 1627.94,430.12 cw(c1699.8,430.12) 1771.65,430.12 1771.65,225.38 2212.59,225.38 2212.59,293.31 cw(c2249.99,293.31) 2287.39,293.31 2287.39,225.38 3791.33,225.38 3791.33,501.97 5944.88,501.97 5944.88,4139.76 -0.01,4139.76 -0.01,177.16

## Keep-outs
L1-Top:
  rectangle: 3791.33,501.97 5433.07,541.34
  rectangle: -0.01,3531.5 499.99,3940.94
L4-BOT:
  rectangle: -0.01,905.51 199.99,3531.5
  rectangle: -0.01,3531.5 499.99,3940.94
  rectangle: 3791.33,501.97 5433.07,541.34
Keep-Out Layer:
  rectangle: 1312.98,177.16 1627.94,312.99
